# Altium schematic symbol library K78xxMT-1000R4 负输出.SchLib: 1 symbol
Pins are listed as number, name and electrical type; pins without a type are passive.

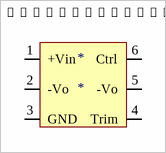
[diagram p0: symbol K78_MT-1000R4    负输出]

## K78_MT-1000R4    负输出
designator *
footprint K78xxMT-500R4 负输出
pins: 1 +Vin, 2 -Vo, 3 GND, 4 Trim, 5 -Vo, 6 Ctrl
